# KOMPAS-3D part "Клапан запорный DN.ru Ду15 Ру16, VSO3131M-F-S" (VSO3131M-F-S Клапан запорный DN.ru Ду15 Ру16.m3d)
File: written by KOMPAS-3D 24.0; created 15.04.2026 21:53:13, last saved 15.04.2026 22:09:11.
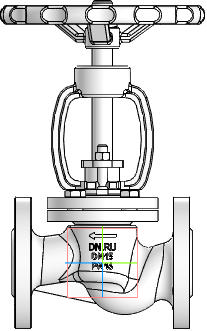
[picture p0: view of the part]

Document properties: Автор: R2D2; Полное имя файла: E:\Работа\Зайцев\VSO3131M-F-S Клапан запорный DN.ru Ду15-100 Ру16\DN15\VSO3131M-F-S Клапан запорный DN.ru Ду15 Ру16.m3d

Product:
- Part/product: Клапан запорный DN.ru Ду15 Ру16  | designation VSO3131M-F-S
    Масса: 3.45
    Раздел спецификации: Прочие изделия
    Примечание: D090-02946

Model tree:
1. Операция без истории:2

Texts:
  VSO3131M-F-S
